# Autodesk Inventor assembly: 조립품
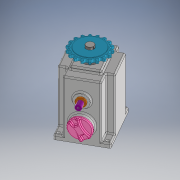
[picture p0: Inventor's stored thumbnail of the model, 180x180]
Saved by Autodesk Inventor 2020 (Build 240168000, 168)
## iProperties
Created: 2022-01
Part Number: 조립품
Document SubType Name: Assembly
Designer: user
Author: user
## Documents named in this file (16)
- C:\Users\user\Desktop\720112V1018\조립품.iam
- C:\Users\user\Desktop\720112V1018\멈춤나사 M3.ipt
- C:\Users\user\Desktop\720112V1018\메인 축.ipt
- C:\Users\user\Desktop\720112V1018\베어링 608.ipt
- C:\Users\user\Desktop\720112V1018\베어링 6003.ipt
- C:\Users\user\Desktop\720112V1018\본체.ipt
- C:\Users\user\Desktop\720112V1018\볼트 M4 x 10.ipt
- C:\Users\user\Desktop\720112V1018\부시.ipt
- C:\Users\user\Desktop\720112V1018\상부 캡.ipt
- C:\Users\user\Desktop\720112V1018\서브 축.ipt
- C:\Users\user\Desktop\720112V1018\스프로킷.ipt
- C:\Users\user\Desktop\720112V1018\슬라이더.ipt
- C:\Users\user\Desktop\720112V1018\오일 실 8 x 22 x 7.ipt
- C:\Users\user\Desktop\720112V1018\오일 실 17 x 32 x 8.ipt
- C:\Users\user\Desktop\720112V1018\커버.ipt
- C:\Users\user\Desktop\720112V1018\키 5 x 5.ipt
